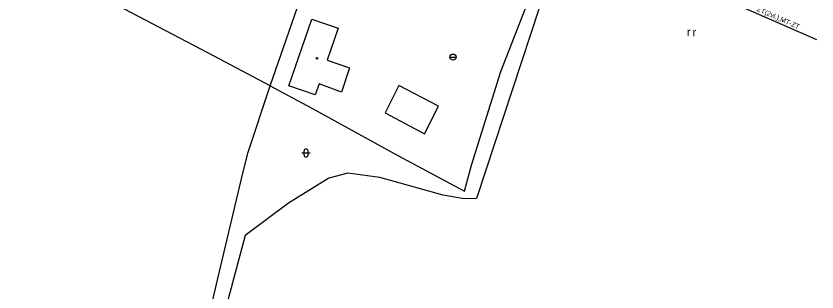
# Model space of a CAD drawing. Extents: x -836739 to -834468, y -1071001 to -1070126.
# Drawn here: x -836438.6 to -836341.2, y -1070459.3 to -1070425.8 of the extents above; entities that cross this region are included whole.
import ezdxf

# ---------------------------------------------------------------- set-up
doc = ezdxf.new("R2010")
doc.units = 0
for name, color, linetype in [('f001_pol_linie', 7, 'Continuous'), ('f001_pol_znacky', 7, 'Continuous'), ('f007_rezkynet_linie', 7, 'Continuous'), ('f007_rezkynet_texty', 7, 'Continuous')]:
    doc.layers.add(name, color=color, linetype=linetype)

msp = doc.modelspace()

# ---------------------------------------------------------------- linework, layer by layer
at = {"layer": 'f001_pol_linie'}
for points in [[(-836407.72, -1070434.26), (-836404.42, -1070424.71), (-836401.63, -1070417.07), (-836396.94, -1070406.16), (-836393.4, -1070397.9)], [(-836407.72, -1070434.26), (-836402.65, -1070436.98), (-836392.21, -1070442.72), (-836384.11, -1070447.06), (-836383.25, -1070443.91), (-836379.69, -1070432.5), (-836376.35, -1070424), (-836370.7, -1070410.27), (-836369.71, -1070407.51)], [(-836407.72, -1070434.26), (-836415.3, -1070430.25), (-836428, -1070423.55), (-836445.87, -1070414.08), (-836449.39, -1070412.25)], [(-836345.8, -1070420.64), (-836355.7, -1070417.34), (-836361.05, -1070417.62), (-836366.07, -1070418.7), (-836371.68, -1070421.97), (-836374.95, -1070424.71), (-836382.62, -1070447.97)], [(-836405.46, -1070434.26), (-836402.66, -1070426.14)], [(-836402.66, -1070426.14), (-836399.46, -1070427.25)], [(-836399.46, -1070427.25), (-836400.8, -1070431.15)], [(-836400.8, -1070431.15), (-836398.08, -1070432.09)], [(-836398.08, -1070432.09), (-836399.05, -1070435.03)], [(-836401.78, -1070434.02), (-836402.26, -1070435.37)], [(-836399.05, -1070435.03), (-836401.78, -1070434.02)], [(-836427.9, -1070546.1), (-836426.76, -1070535.49), (-836425.46, -1070522.59), (-836424.54, -1070513.97), (-836423.07, -1070499.04), (-836421.63, -1070492.15), (-836418.84, -1070478.02), (-836414.08, -1070457.69), (-836411.22, -1070445.56), (-836410.44, -1070442.44), (-836407.72, -1070434.26)], [(-836402.26, -1070435.37), (-836405.46, -1070434.26)], [(-836387.27, -1070436.75), (-836392.07, -1070434.23), (-836393.73, -1070437.54), (-836388.97, -1070440.09), (-836387.27, -1070436.75)], [(-836382.62, -1070447.97), (-836384.12, -1070448.01), (-836386.69, -1070447.56), (-836394.4, -1070445.42), (-836398.28, -1070444.88), (-836400.59, -1070445.48), (-836405.51, -1070448.52), (-836410.77, -1070452.46), (-836414.78, -1070467.48), (-836419.92, -1070491.57), (-836422.14, -1070507.07), (-836424.43, -1070527.13), (-836426.86, -1070555.21), (-836427.73, -1070571.17), (-836426.62, -1070578.67)]]:
    msp.add_lwpolyline(points, dxfattribs=at)
at = {"layer": 'f001_pol_znacky'}
for p, q in [((-836385.855, -1070430.77), (-836385.105, -1070430.77)), ((-836403.86, -1070442.43), (-836402.86, -1070442.43)), ((-836403.61, -1070442.68), (-836403.61, -1070442.18)), ((-836403.11, -1070442.68), (-836403.11, -1070442.18))]:
    msp.add_line(p, q, dxfattribs=at)
for centre, radius in [((-836402.04, -1070430.91), 0.0875), ((-836385.48, -1070430.77), 0.375)]:
    msp.add_circle(centre, radius, dxfattribs=at)
for centre, start, end in [((-836403.36, -1070442.18), 0, 179.99999), ((-836403.36, -1070442.68), 179.99999, 359.99999)]:
    msp.add_arc(centre, 0.25, start, end, dxfattribs=at)
at = {"layer": 'f007_rezkynet_linie'}
msp.add_lwpolyline([(-836341.211, -1070428.682), (-836353.103, -1070423.416), (-836352.583, -1070421.575)], dxfattribs=at)

# ---------------------------------------------------------------- texts
at = {"layer": 'f001_pol_znacky'}
for p in [(-836357.038, -1070428.202), (-836356.358, -1070428.252)]:
    msp.add_text('r', height=1, dxfattribs=at).set_placement(p)
at = {"layer": 'f007_rezkynet_texty'}
msp.add_text('O/CC,8xMT-ZT(2vl.),MT-ZT', height=0.6, rotation=336.11529, dxfattribs=at).set_placement((-836352.83, -1070423.257))

doc.saveas('drawing.dxf')
